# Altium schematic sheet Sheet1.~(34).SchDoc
size A; SheetNumber: 1; SheetTotal: 1
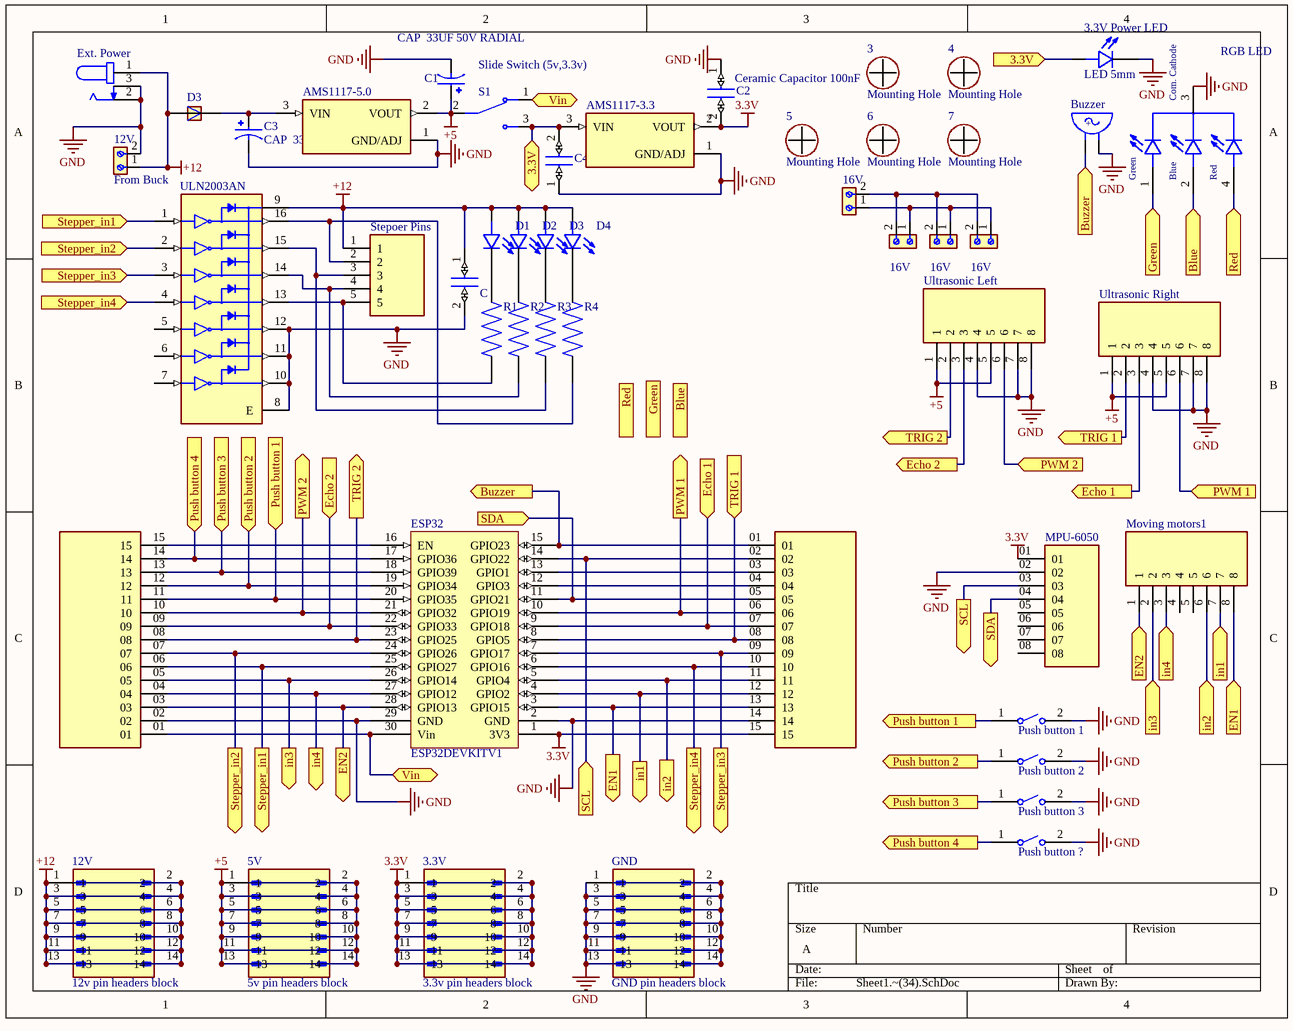
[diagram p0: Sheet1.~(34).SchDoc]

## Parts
(Parts that share a designator on the sheet are numbered #1, #2 ... from top to bottom, then left to right.)
3  Mounting Hole  [PCBComponent_1]
3.3V  3.3v pin headers block  [AMPHENOL_52601-S14-4LF]
3.3V_Power_LED  LED 5mm  [LED 5mm]
4  Mounting Hole  [PCBComponent_1]
5  Mounting Hole  [PCBComponent_1]
5V  5v pin headers block  [AMPHENOL_52601-S14-4LF]
6  Mounting Hole  [PCBComponent_1]
7  Mounting Hole  [PCBComponent_1]
12V#1  From Buck  [691213510002]
12V#2  12v pin headers block  [AMPHENOL_52601-S14-4LF]
16V#1  From Buck  [691213510002]  (value not drawn)
16V#2  From Buck  [691213510002]  (value not drawn)
16V#3  From Buck  [691213510002]  (value not drawn)
16V#4  From Buck  [691213510002]  (value not drawn)
AMS1117-3.3  AMS1117-3.3  [SOT229P700X180-4N]  (value not drawn)
AMS1117-5.0  AMS1117-5.0  [SOT229P700X180-4N]  (value not drawn)
Buzzer  Buzzer  [Buzzer 5V]  (value not drawn)
C  Ceramic Capacitor 100nF  [C320C]  (value not drawn)
C1  CAP  33UF 50V RADIAL  [CAP  33UF 50V RADIAL]
C2  Ceramic Capacitor 100nF  [C320C]
C3  CAP  33UF 50V RADIAL  [CAP  33UF 50V RADIAL]
C4  Ceramic Capacitor 100nF  [C320C]  (value not drawn)
D1  LED 5mm  [LED 5mm]  (value not drawn)
D2  LED 5mm  [LED 5mm]  (value not drawn)
D3#1  RL207  [DIOAD1300W80L670D310]  (value not drawn)
D3#2  LED 5mm  [LED 5mm]  (value not drawn)
D4  LED 5mm  [LED 5mm]  (value not drawn)
ESP32  ESP32DEVKITV1  [ESP32DEVKITV1]
Ext._Power  DC Power Jack Female Socket  [DC Power Jack Female Socket]  (value not drawn)
GND  GND pin headers block  [AMPHENOL_52601-S14-4LF]
J5  TS-115-T-A-1  [SAMTEC_TS-115-T-A-1]  (value not drawn)
J6  TS-115-T-A-1  [SAMTEC_TS-115-T-A-1]  (value not drawn)
Moving_motors1  Pin header female block 8 pin  [Pin header female block 8 pin]  (value not drawn)
MPU-6050  MPU-6050  [MPU-6050]  (value not drawn)
Push_button_1  FSM8JRT  [TE_FSM8JRT]  (value not drawn)
Push_button_2  FSM8JRT  [TE_FSM8JRT]  (value not drawn)
Push_button_3  FSM8JRT  [TE_FSM8JRT]  (value not drawn)
Push_button_?  FSM8JRT  [TE_FSM8JRT]  (value not drawn)
R1  Resistor  [RESAD700W45L350D185]  (value not drawn)
R2  Resistor  [RESAD700W45L350D185]  (value not drawn)
R3  Resistor  [RESAD700W45L350D185]  (value not drawn)
R4  Resistor  [RESAD700W45L350D185]  (value not drawn)
RGB_LED  common cathode  [LED RGB 5mm]  (value not drawn)
S1  Slide Switch (5v,3.3v)  [Slide switch]
Stepoer_Pins  Pin hreader 5 pins  [Pin hreader 5 pins]  (value not drawn)
ULN2003AN  ULN2003AN  [DIP794W45P254L1969H508Q16]  (value not drawn)
Ultrasonic_Left  Pin header female block 8 pin  [Pin header female block 8 pin]  (value not drawn)
Ultrasonic_Right  Pin header female block 8 pin  [Pin header female block 8 pin]  (value not drawn)

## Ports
3.3V (bidir, see Sheet1[4A]), 3.3V (in, see Sheet1[2A]), Blue (in, see Sheet1[3B]), Blue (out, see Sheet1[4B]), Buzzer (in, see Sheet1[2B]), Buzzer (out, see Sheet1[4A]), Echo 1 (in, see Sheet1[4B]), Echo 1 (out, see Sheet1[3C]), Echo 2 (in, see Sheet1[3B]), Echo 2 (out, see Sheet1[2C]), EN1 (in, see Sheet1[2D]), EN1 (out, see Sheet1[4C]), EN2 (in, see Sheet1[2D]), EN2 (out, see Sheet1[4C]), Green (in, see Sheet1[3B]), Green (out, see Sheet1[4B]), in1 (in, see Sheet1[2D]), in1 (out, see Sheet1[4C]), in2 (in, see Sheet1[3D]), in2 (out, see Sheet1[4C]), in3 (in, see Sheet1[1D]), in3 (out, see Sheet1[4C]), in4 (in, see Sheet1[1D]), in4 (out, see Sheet1[4C]), Push button 1 (in, see Sheet1[3C]), Push button 1 (out, see Sheet1[1C]), Push button 2 (in, see Sheet1[3C]), Push button 2 (out, see Sheet1[1C]), Push button 3 (in, see Sheet1[3D]), Push button 3 (out, see Sheet1[1C]), Push button 4 (in, see Sheet1[3D]), Push button 4 (out, see Sheet1[1C]), PWM 1 (in, see Sheet1[3C]), PWM 1 (out, see Sheet1[4B]), PWM 2 (in, see Sheet1[1C]), PWM 2 (out, see Sheet1[4B]), Red (in, see Sheet1[2B]), Red (out, see Sheet1[4B]), SCL (in, see Sheet1[3C]), SCL (out, see Sheet1[2D]), SDA (in, see Sheet1[4C]), SDA (out, see Sheet1[2C]), Stepper_in1 (in, see Sheet1[1D]), Stepper_in1 (out, see Sheet1[1A]), Stepper_in2 (in, see Sheet1[1D]), Stepper_in2 (out, see Sheet1[1A]), Stepper_in3 (in, see Sheet1[3D]), Stepper_in3 (out, see Sheet1[1B]), Stepper_in4 (in, see Sheet1[3D]), Stepper_in4 (out, see Sheet1[1B]), TRIG 1 (in, see Sheet1[4B]), TRIG 1 (out, see Sheet1[3C]), TRIG 2 (out, see Sheet1[2C]), TRIG 2 (out, see Sheet1[3B]), Vin (bidir, see Sheet1[2A]), Vin (bidir, see Sheet1[2D])

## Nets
3.3V: 3.3V.1 3.3V.2 3.3V.3 3.3V.4 3.3V.5 3.3V.6 3.3V.7 3.3V.8 3.3V.9 3.3V.10 3.3V.11 3.3V.12 3.3V.13 3.3V.14 AMS1117-3.3.2(VOUT) C2.2 ESP32.1(3V3) J5.15 MPU-6050.01
+5: 5V.1 5V.2 5V.3 5V.4 5V.5 5V.6 5V.7 5V.8 5V.9 5V.10 5V.11 5V.12 5V.13 5V.14 AMS1117-5.0.2(VOUT) C1.P S1.2 Ultrasonic_Left.1 Ultrasonic_Left.5 Ultrasonic_Right.1 Ultrasonic_Right.5
+12: 12V#1.1 12V#2.1 12V#2.2 12V#2.3 12V#2.4 12V#2.5 12V#2.6 12V#2.7 12V#2.8 12V#2.9 12V#2.10 12V#2.11 12V#2.12 12V#2.13 12V#2.14 C.1 D1.A D2.A D3#1.A D3#2.A D4.A Ext._Power.1 Stepoer_Pins.1 ULN2003AN.9(COM)
GND: 3.3V_Power_LED.C 12V#1.2 AMS1117-3.3.1(GND/ADJ) AMS1117-5.0.1(GND/ADJ) Buzzer.NEG C.2 C1.N C2.1 C3.N C4.1 ESP32.2(GND) ESP32.29(GND) Ext._Power.2 Ext._Power.3 GND.1 GND.2 GND.3 GND.4 GND.5 GND.6 GND.7 GND.8 GND.9 GND.10 GND.11 GND.12 GND.13 GND.14 J5.14 J6.02 MPU-6050.02 Push_button_1.2 Push_button_2.2 Push_button_3.2 Push_button_?.2 RGB_LED.3(Com._Cathode) ULN2003AN.8(E) ULN2003AN.10(7C) ULN2003AN.11(6C) ULN2003AN.12(5C) Ultrasonic_Left.4 Ultrasonic_Left.7 Ultrasonic_Left.8 Ultrasonic_Right.4 Ultrasonic_Right.7 Ultrasonic_Right.8
3.3V: 3.3V_Power_LED.A AMS1117-3.3.3(VIN) C4.2 S1.3 ; port 3.3V  [a separate net that carries the same name]
Blue: RGB_LED.2(BLUE) ; port Blue
Buzzer: Buzzer.POS ESP32.15(GPIO23) J5.01 ; port Buzzer
Echo 1: ESP32.9(GPIO18) J5.07 Ultrasonic_Right.3 ; port Echo 1
Echo 2: ESP32.22(GPIO33) J6.09 Ultrasonic_Left.3 ; port Echo 2
EN1: ESP32.3(GPIO15) J5.13 Moving_motors1.8 ; port EN1
EN2: ESP32.28(GPIO13) J6.03 Moving_motors1.1 ; port EN2
Green: RGB_LED.1(Green) ; port Green
in1: ESP32.4(GPIO2) J5.12 Moving_motors1.7 ; port in1
in2: ESP32.5(GPIO4) J5.11 Moving_motors1.6 ; port in2
in3: ESP32.26(GPIO14) J6.05 Moving_motors1.2 ; port in3
in4: ESP32.27(GPIO12) J6.04 Moving_motors1.3 ; port in4
Push button 1: ESP32.20(GPIO35) J6.11 Push_button_1.1 ; port Push button 1
Push button 2: ESP32.19(GPIO34) J6.12 Push_button_2.1 ; port Push button 2
Push button 3: ESP32.18(GPIO39) J6.13 Push_button_3.1 ; port Push button 3
Push button 4: ESP32.17(GPIO36) J6.14 Push_button_?.1 ; port Push button 4
PWM 1: ESP32.10(GPIO19) J5.06 Ultrasonic_Right.6 ; port PWM 1
PWM 2: ESP32.21(GPIO32) J6.10 Ultrasonic_Left.6 ; port PWM 2
Red: RGB_LED.4(Red) ; port Red
SCL: ESP32.14(GPIO22) J5.02 MPU-6050.03 ; port SCL
SDA: ESP32.11(GPIO21) J5.05 MPU-6050.04 ; port SDA
Stepper_in1: ESP32.25(GPIO27) J6.06 ULN2003AN.1(1B) ; port Stepper_in1
Stepper_in2: ESP32.24(GPIO26) J6.07 ULN2003AN.2(2B) ; port Stepper_in2
Stepper_in3: ESP32.7(GPIO17) J5.09 ULN2003AN.3(3B) ; port Stepper_in3
Stepper_in4: ESP32.6(GPIO16) J5.10 ULN2003AN.4(4B) ; port Stepper_in4
TRIG 1: ESP32.8(GPIO5) J5.08 Ultrasonic_Right.2 ; port TRIG 1
TRIG 2: ESP32.23(GPIO25) J6.08 Ultrasonic_Left.2 ; port TRIG 2
Vin: ESP32.30(Vin) J6.01 S1.1 ; port Vin
Net16V#1_1: 16V#1.1 16V#2.1 16V#3.1 16V#4.1
Net16V#1_2: 16V#1.2 16V#2.2 16V#3.2 16V#4.2
NetAMS1117-5.0_3: AMS1117-5.0.3(VIN) C3.P D3#1.C
NetD1_C: D1.C R1.2
NetD2_C: D2.C R2.2
NetD3#2_C: D3#2.C R3.2
NetD4_C: D4.C R4.2
NetESP32_12: ESP32.12(GPIO3) J5.04
NetESP32_13: ESP32.13(GPIO1) J5.03
NetESP32_16: ESP32.16(EN) J6.15
NetR1_1: R1.1 Stepoer_Pins.5 ULN2003AN.13(4C)
NetR2_1: R2.1 Stepoer_Pins.4 ULN2003AN.14(3C)
NetR3_1: R3.1 Stepoer_Pins.3 ULN2003AN.15(2C)
NetR4_1: R4.1 Stepoer_Pins.2 ULN2003AN.16(1C)

Not connected (* = marked no-connect by the designer): Moving_motors1 4 5; MPU-6050 05 06 07 08; ULN2003AN 5(5B) 6(6B) 7(7B)

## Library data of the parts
3.3V 5V 12V#2 GND = 52601-S14-4LF: MF: {'manufacturer': u'Amphenol ICC (FCI)'}
3.3V_Power_LED D1 D2 D3#2 D4 = LED 5mm: Red 623nm LED Indication - Discrete 1.9V Radial; MF: {'manufacturer': u'Wurth Elektronik'}; MP: 151054RS03000
12V#1 16V#1-16V#4 = Terminal Block: 2 Position Wire to Board Terminal Block Horizontal with Board 0.200 (5.08mm) Through Hole; MF: Wurth Electronics
AMS1117-3.3 = AMS1117-3.3: MF: {'manufacturer': u'Advanced Monolithic Systems'}
AMS1117-5.0 = AMS1117-5.0: MF: {'manufacturer': u'Advanced Monolithic Systems'}
Buzzer = Buzzer 5V: BUZZER 2.3KHZ 4-6VDC; MF: {'manufacturer': u'Soberton Inc.'}; MP: WST-1205S
C C2 C4 = Ceramic Capacitor 100nF: 0.1ÂµF Â±20% 50V Ceramic Capacitor Z5U Radial; MF: KEMET; MP: C320C104M5U5TA
C1 C3 = CAP  33UF 50V RADIAL: NHG-A; MF: {'manufacturer': u'Panasonic'}; MP: ECA1HHG330I
D3#1 = RL207: Semiconductors and Actives, Power Diodes, Discretes (diodes, transistors, thyristors ...), Diodes; MF: {'manufacturer': u'Diodes Inc.'}
Ext._Power = DC Power Jack Female Socket: 2.0 mm Center Pin, 2.5 A, Right Angle, Through Hole, Dc Power Jack Connector; MF: {'manufacturer': u'CUI Devices'}; MP: PJ-002A
J5 J6 = TS-115-T-A-1: MF: {'manufacturer': u'Samtec'}
Moving_motors1 Ultrasonic_Left Ultrasonic_Right = Pin header female block 8 pin: MF: {'manufacturer': u'TE Connectivity'}; MP: 5-534998-4
Push_button_1-Push_button_3 Push_button_? = FSM8JRT: Tactile Switches PUSHBUTTON SWITCH TACT; MF: {'manufacturer': u'TE Connectivity'}
R1-R4 = Resistor: CFR16 5% 10K; MF: {'manufacturer': u'TE Connectivity'}; MP: 2-1623927-3
RGB_LED = LED RGB 5mm: MF: {'manufacturer': u'Kingbright'}; MP: WP154A4SUREQBFZGC
S1 = Slide switch: MF: {'manufacturer': u'E-Switch'}; MP: EG1206
Stepoer_Pins = Pin hreader 5 pins: MF: {'manufacturer': u'TE Connectivity'}; MP: 2355181-5
ULN2003AN = ULN2003AN: MF: {'manufacturer': u'Texas Instruments'}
